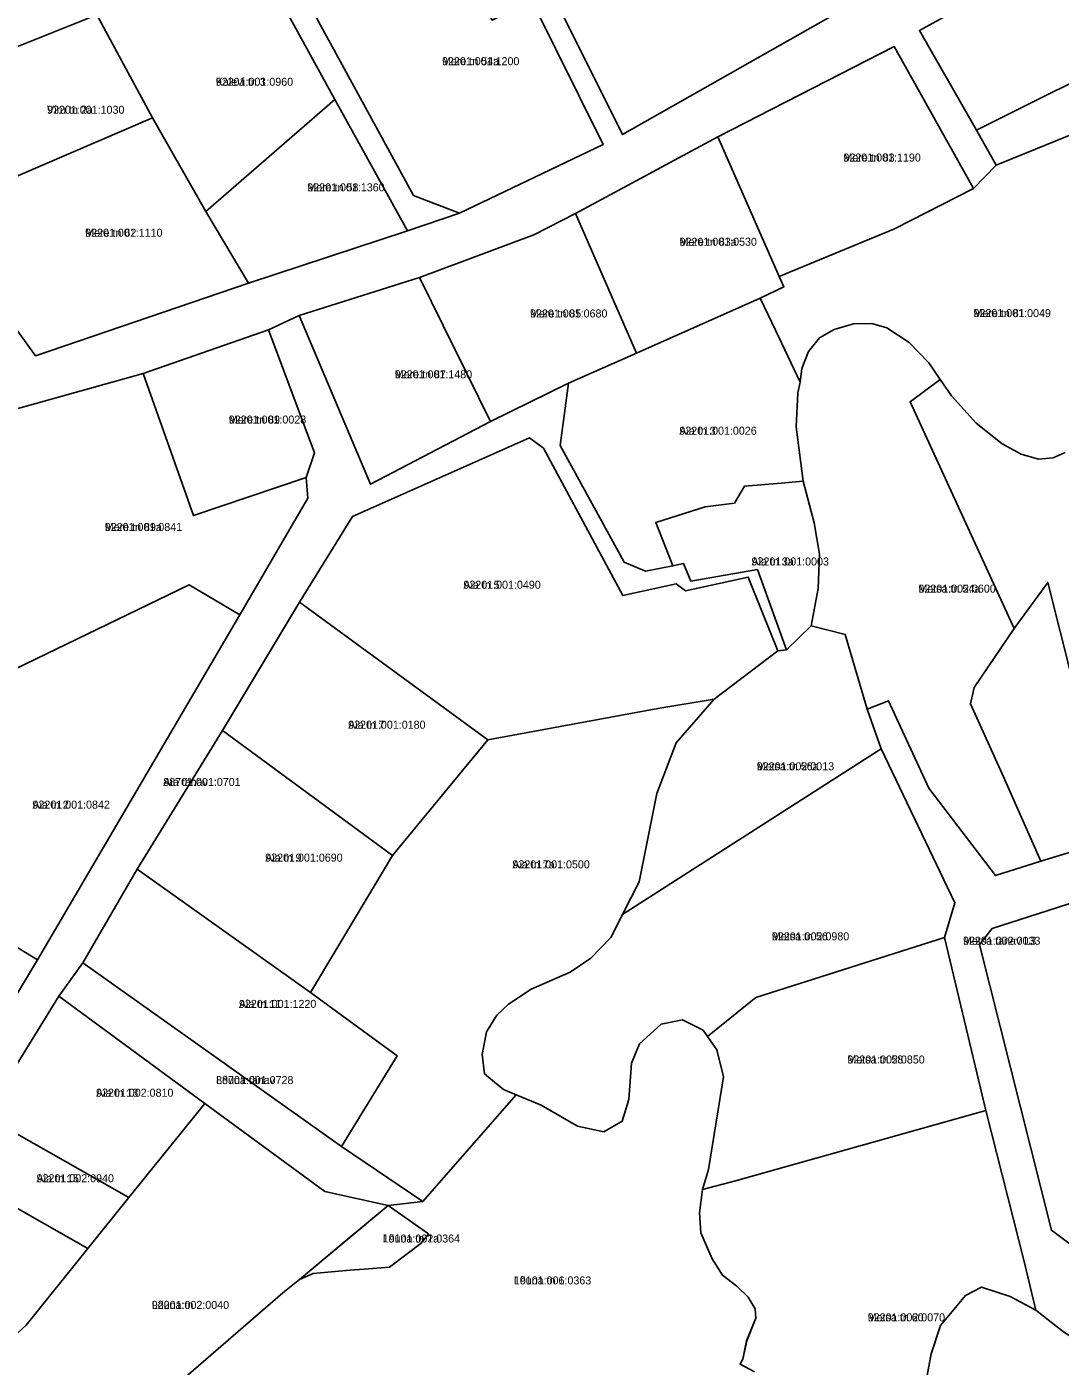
# Model space of a CAD drawing. Extents: x 601493 to 643081, y 6584980 to 6634019.
# Drawn here: x 610425.7 to 610619.4, y 6605570.9 to 6605821.9 of the extents above; entities that cross this region are included whole.
import ezdxf

# ---------------------------------------------------------------- set-up
doc = ezdxf.new("R2010")
doc.units = 0
for name, color, linetype in [('L_AADRESS', 7, 'Continuous'), ('PIIR', 7, 'Continuous'), ('TUNNUS', 7, 'Continuous')]:
    doc.layers.add(name, color=color, linetype=linetype)

msp = doc.modelspace()

# ---------------------------------------------------------------- linework, layer by layer
at = {"layer": 'PIIR'}
for points in [[(610409.51, 6605943.56), (610413.06, 6605945.52), (610442.84, 6605891.09), (610453, 6605873.21), (610473.31, 6605835.94), (610498.14, 6605790.29), (610506.76, 6605787.04), (610497.03, 6605783.72), (610483.4, 6605808.34), (610468.44, 6605835.69), (610458.2, 6605853.78), (610439.63, 6605888.64), (610429.91, 6605906.72)], [(610523.75, 6605829.01), (610538.97, 6605837.66), (610524.32, 6605864.07), (610549.39, 6605877.83), (610568.15, 6605844.43), (610579.58, 6605825.71), (610537.37, 6605801.75)], [(610407.64, 6605815.07), (610401, 6605826.74), (610398.53, 6605831.24), (610402.16, 6605833.25), (610458.2, 6605853.78), (610468.44, 6605835.69), (610438.77, 6605824.16), (610408.41, 6605812.08)], [(610473.31, 6605835.94), (610498.95, 6605849.93), (610512.93, 6605823.21), (610520.28, 6605826.94), (610533.7, 6605799.87), (610506.76, 6605787.04), (610498.14, 6605790.29)], [(610593.01, 6605821.27), (610636.89, 6605845.42), (610653.37, 6605817.46), (610639.31, 6605810.75), (610634.12, 6605817.74), (610603.72, 6605802.55)], [(610449.26, 6605804.89), (610438.77, 6605824.16), (610468.44, 6605835.69), (610483.4, 6605808.34), (610459.22, 6605787.33)], [(610401.39, 6605794.31), (610411.76, 6605799.04), (610408.41, 6605812.08), (610438.77, 6605824.16), (610449.26, 6605804.89), (610407.9, 6605787.12)], [(610566.71, 6605775.15), (610555.22, 6605801.29), (610588.26, 6605818.23), (610603.12, 6605791.61), (610588.35, 6605784.07)], [(610634.12, 6605817.74), (610639.31, 6605810.75), (610652.09, 6605787.88), (610652.85, 6605786.44), (610636.44, 6605776.8), (610622.16, 6605801.98), (610607.42, 6605796.01), (610603.72, 6605802.55)], [(610459.22, 6605787.33), (610483.4, 6605808.34), (610497.03, 6605783.72), (610467.24, 6605773.86)], [(610407.9, 6605787.12), (610449.26, 6605804.89), (610459.22, 6605787.33), (610467.24, 6605773.86), (610427.28, 6605760.29)], [(610539.94, 6605760.78), (610528.51, 6605786.94), (610555.22, 6605801.29), (610566.71, 6605775.15), (610567.56, 6605773.2), (610563.17, 6605771.06)], [(610499.29, 6605774.98), (610520.75, 6605782.97), (610528.51, 6605786.94), (610539.94, 6605760.78), (610527.23, 6605755.17), (610512.6, 6605747.99)], [(610490.07, 6605736.19), (610476.7, 6605767.8), (610499.29, 6605774.98), (610512.6, 6605747.99)], [(610527.23, 6605755.17), (610539.94, 6605760.78), (610563.17, 6605771.06), (610566, 6605765.1), (610570.64, 6605755.33), (610570.22, 6605753.32), (610569.87, 6605746.98), (610571.24, 6605736.77), (610567.08, 6605736.42), (610560.23, 6605735.85), (610558.31, 6605732.62), (610552.85, 6605731.98), (610543.56, 6605729), (610546.8, 6605720.92), (610541.66, 6605719.89), (610537.66, 6605721.59), (610525.67, 6605743.47)], [(610583.22, 6605694.06), (610579.09, 6605708.04), (610572.73, 6605709.65), (610574.02, 6605716.67), (610574.27, 6605723.1), (610573.29, 6605728.95), (610571.24, 6605736.77), (610569.87, 6605746.98), (610570.22, 6605753.32), (610570.64, 6605755.33), (610570.98, 6605757.9), (610572.19, 6605761.07), (610574.28, 6605763.67), (610577.03, 6605765.2), (610580.62, 6605766.25), (610584.1, 6605766.3), (610586.91, 6605765.53), (610591.06, 6605762.74), (610594.74, 6605758.98), (610596.92, 6605755.86), (610591.27, 6605751.67), (610610.74, 6605709.16), (610603.27, 6605698.07), (610602.57, 6605695.06), (610608.77, 6605681.37), (610615.77, 6605665.54), (610607.24, 6605662.85), (610594.78, 6605679.22), (610587.21, 6605695.63)], [(610447.51, 6605756.94), (610470.96, 6605765.17), (610479.57, 6605742.08), (610478.03, 6605737.44), (610456.9, 6605730.33)], [(610400.23, 6605743.76), (610447.51, 6605756.94), (610456.9, 6605730.33), (610478.03, 6605737.44), (610478.38, 6605733.58), (610465.58, 6605711.74), (610456.1, 6605717.35), (610415.85, 6605697.91)], [(610476.79, 6605714.12), (610486.71, 6605730.17), (610519.9, 6605744.92), (610522.53, 6605742.95), (610537.39, 6605715.33), (610547.42, 6605717.56), (610549.14, 6605716.22), (610560.92, 6605718.79), (610563.44, 6605712.42), (610566.49, 6605704.97), (610554.54, 6605695.93), (610543.95, 6605694.16), (610512.09, 6605688.29)], [(610543.56, 6605729), (610552.85, 6605731.98), (610558.31, 6605732.62), (610560.23, 6605735.85), (610567.08, 6605736.42), (610571.24, 6605736.77), (610573.29, 6605728.95), (610574.27, 6605723.1), (610574.02, 6605716.67), (610572.73, 6605709.65), (610568.08, 6605705.17), (610566.76, 6605708.81), (610562.66, 6605720.2), (610550.17, 6605718.04), (610548.75, 6605721.32), (610546.8, 6605720.92)], [(610387.89, 6605678.79), (610415.85, 6605697.91), (610456.1, 6605717.35), (610465.58, 6605711.74), (610427.67, 6605647.04), (610390.42, 6605669.77)], [(610608.77, 6605681.37), (610602.57, 6605695.06), (610603.27, 6605698.07), (610610.74, 6605709.16), (610617.06, 6605717.8), (610621.73, 6605699.44), (610633.98, 6605703.42), (610638.2, 6605691.66), (610644.68, 6605674.38), (610615.77, 6605665.54)], [(610512.09, 6605688.29), (610494.23, 6605666.62), (610462.38, 6605690.01), (610476.79, 6605714.12)], [(610572.73, 6605709.65), (610579.09, 6605708.04), (610583.22, 6605694.06), (610585.84, 6605686.6), (610546.41, 6605661.33), (610537.33, 6605655.52), (610540.49, 6605661.69), (610543.78, 6605678.25), (610547.4, 6605687.73), (610554.54, 6605695.93), (610566.49, 6605704.97), (610568.08, 6605705.17)], [(610527.51, 6605644.71), (610520.23, 6605641.56), (610515.98, 6605638.77), (610513.8, 6605636.71), (610511.86, 6605633.55), (610511.01, 6605629.3), (610511.49, 6605625.67), (610513.34, 6605624.14), (610515.01, 6605622.75), (610517.42, 6605621.76), (610513.38, 6605617.16), (610499.88, 6605601.76), (610484.69, 6605612.05), (610495.08, 6605629.08), (610478.88, 6605640.9), (610494.23, 6605666.62), (610512.09, 6605688.29), (610543.95, 6605694.16), (610554.54, 6605695.93), (610547.4, 6605687.73), (610543.78, 6605678.25), (610540.49, 6605661.69), (610537.33, 6605655.52), (610535.15, 6605651.26), (610531.39, 6605647.38)], [(610462.38, 6605690.01), (610494.23, 6605666.62), (610478.88, 6605640.9), (610446.34, 6605664.04)], [(610544.6, 6605634.99), (610540.53, 6605631.33), (610539.06, 6605627.68), (610538.54, 6605620.89), (610537.28, 6605616.81), (610533.84, 6605614.83), (610528.93, 6605615.87), (610522.07, 6605619.84), (610517.42, 6605621.76), (610515.01, 6605622.75), (610513.34, 6605624.14), (610511.49, 6605625.67), (610511.01, 6605629.3), (610511.86, 6605633.55), (610513.8, 6605636.71), (610515.98, 6605638.77), (610520.23, 6605641.56), (610527.51, 6605644.71), (610531.39, 6605647.38), (610535.15, 6605651.26), (610537.33, 6605655.52), (610546.41, 6605661.33), (610585.84, 6605686.6), (610599.65, 6605657.71), (610597.73, 6605651.24), (610562.34, 6605639.98), (610553.25, 6605632.7), (610552.44, 6605633.84), (610548.57, 6605635.82)], [(610382.27, 6605663.31), (610380.71, 6605667.07), (610390.42, 6605669.77), (610427.67, 6605647.04), (610404.86, 6605609.15), (610363.87, 6605656.09)], [(610446.34, 6605664.04), (610478.88, 6605640.9), (610495.08, 6605629.08), (610484.69, 6605612.05), (610436.17, 6605646.51)], [(610617.75, 6605596.36), (610604.29, 6605649.91), (610606.64, 6605652.9), (610629.58, 6605660.29), (610636.59, 6605616.03), (610658.53, 6605609.22), (610661.08, 6605608.5), (610661.53, 6605606.06), (610664.72, 6605596.68), (610669.26, 6605589.77), (610671.34, 6605586.86), (610672.35, 6605585.44), (610671.52, 6605581.73), (610669.15, 6605577.6), (610664.09, 6605574.82), (610653.47, 6605575.75), (610648.01, 6605576.06), (610646.85, 6605574.99), (610637.1, 6605581.95)], [(610552.34, 6605604.01), (610553.46, 6605607.77), (610556.27, 6605625.1), (610555.05, 6605630.18), (610553.25, 6605632.7), (610562.34, 6605639.98), (610597.73, 6605651.24), (610605.44, 6605618.8), (610558.54, 6605605.61)], [(610436.17, 6605646.51), (610484.69, 6605612.05), (610499.88, 6605601.76), (610493.38, 6605601), (610481.55, 6605603.61), (610459.02, 6605620.13), (610431.69, 6605640.26)], [(610431.69, 6605640.26), (610459.02, 6605620.13), (610444.82, 6605602.51), (610417.77, 6605617.8)], [(610425.55, 6605578.59), (610437.08, 6605592.92), (610444.82, 6605602.51), (610459.02, 6605620.13), (610481.55, 6605603.61), (610493.38, 6605601), (610476.79, 6605587.15), (610473.64, 6605584.61), (610451.8, 6605565.68), (610448.69, 6605563.75), (610435.15, 6605554.82), (610421.65, 6605548.04), (610419.3, 6605547.36), (610404.58, 6605543.12), (610393.75, 6605545.93), (610399.96, 6605555.08)], [(610417.77, 6605617.8), (610444.82, 6605602.51), (610437.08, 6605592.92), (610412.26, 6605607.05)], [(610412.26, 6605607.05), (610437.08, 6605592.92), (610425.55, 6605578.59), (610399.96, 6605555.08), (610383.24, 6605558.65)], [(610485.29, 6605594.26), (610493.38, 6605601), (610500.78, 6605595.79), (610500.98, 6605595.65), (610500.3, 6605594.82), (610499.56, 6605593.91), (610493.68, 6605589.47), (610488.91, 6605589.07), (610486.25, 6605588.85), (610479.34, 6605588.25), (610476.79, 6605587.15)]]:
    msp.add_lwpolyline(points, close=True, dxfattribs=at)
for points in [[(610636.89, 6605845.42), (610593.01, 6605821.27), (610603.72, 6605802.55), (610607.42, 6605796.01), (610603.12, 6605791.61), (610588.26, 6605818.23), (610555.22, 6605801.29), (610528.51, 6605786.94), (610520.75, 6605782.97), (610499.29, 6605774.98), (610476.7, 6605767.8), (610470.96, 6605765.17), (610447.51, 6605756.94), (610400.23, 6605743.76)], [(610523.75, 6605829.01), (610537.37, 6605801.75), (610579.58, 6605825.71)], [(610407.9, 6605787.12), (610427.28, 6605760.29), (610467.24, 6605773.86), (610497.03, 6605783.72), (610506.76, 6605787.04), (610533.7, 6605799.87), (610520.28, 6605826.94)], [(610620.36, 6605742.15), (610618.06, 6605741.14), (610615.34, 6605740.91), (610612.06, 6605741.84), (610608.5, 6605743.79), (610603.67, 6605747.67), (610599.04, 6605752.8), (610596.92, 6605755.86), (610594.74, 6605758.98), (610591.06, 6605762.74), (610586.91, 6605765.53), (610584.1, 6605766.3), (610580.62, 6605766.25), (610577.03, 6605765.2), (610574.28, 6605763.67), (610572.19, 6605761.07), (610570.98, 6605757.9), (610570.64, 6605755.33), (610566, 6605765.1), (610563.17, 6605771.06), (610567.56, 6605773.2), (610566.71, 6605775.15), (610588.35, 6605784.07), (610603.12, 6605791.61), (610607.42, 6605796.01), (610622.16, 6605801.98)], [(610404.86, 6605609.15), (610427.67, 6605647.04), (610465.58, 6605711.74), (610478.38, 6605733.58), (610478.03, 6605737.44), (610479.57, 6605742.08), (610470.96, 6605765.17), (610476.7, 6605767.8), (610490.07, 6605736.19), (610512.6, 6605747.99), (610527.23, 6605755.17), (610525.67, 6605743.47), (610537.66, 6605721.59), (610541.66, 6605719.89), (610546.8, 6605720.92), (610548.75, 6605721.32), (610550.17, 6605718.04), (610562.66, 6605720.2), (610566.76, 6605708.81), (610568.08, 6605705.17), (610566.49, 6605704.97), (610563.44, 6605712.42), (610560.92, 6605718.79), (610549.14, 6605716.22), (610547.42, 6605717.56), (610537.39, 6605715.33), (610522.53, 6605742.95), (610519.9, 6605744.92), (610486.71, 6605730.17), (610476.79, 6605714.12), (610462.38, 6605690.01), (610446.34, 6605664.04), (610436.17, 6605646.51), (610431.69, 6605640.26), (610417.77, 6605617.8)], [(610621.73, 6605699.44), (610617.06, 6605717.8), (610610.74, 6605709.16), (610591.27, 6605751.67), (610596.92, 6605755.86), (610599.04, 6605752.8), (610603.67, 6605747.67), (610608.5, 6605743.79), (610612.06, 6605741.84), (610615.34, 6605740.91), (610618.06, 6605741.14), (610620.36, 6605742.15)], [(610762.69, 6605727.65), (610736.99, 6605718.1), (610741.9, 6605692.35), (610736.92, 6605690.82), (610713.75, 6605683.91), (610696.11, 6605679.21), (610703.58, 6605649.99), (610698.8, 6605648.75), (610691.49, 6605678.3), (610680.02, 6605674.96), (610656.94, 6605668.21), (610629.58, 6605660.29), (610606.64, 6605652.9), (610604.29, 6605649.91), (610617.75, 6605596.36), (610637.1, 6605581.95), (610646.85, 6605574.99), (610645.12, 6605573.38), (610644.87, 6605572.95), (610641.1, 6605566.37)], [(610620, 6605577.34), (610614.85, 6605581.36), (610612.66, 6605590.5), (610605.44, 6605618.8), (610597.73, 6605651.24), (610599.65, 6605657.71), (610585.84, 6605686.6), (610583.22, 6605694.06), (610587.21, 6605695.63), (610594.78, 6605679.22), (610607.24, 6605662.85), (610615.77, 6605665.54), (610644.68, 6605674.38)], [(610451.8, 6605565.68), (610473.64, 6605584.61), (610476.79, 6605587.15), (610479.34, 6605588.25), (610486.25, 6605588.85), (610488.91, 6605589.07), (610493.68, 6605589.47), (610499.56, 6605593.91), (610500.3, 6605594.82), (610500.98, 6605595.65), (610500.78, 6605595.79), (610493.38, 6605601), (610499.88, 6605601.76), (610513.38, 6605617.16), (610517.42, 6605621.76), (610522.07, 6605619.84), (610528.93, 6605615.87), (610533.84, 6605614.83), (610537.28, 6605616.81), (610538.54, 6605620.89), (610539.06, 6605627.68), (610540.52, 6605631.33), (610544.6, 6605634.99), (610548.57, 6605635.82), (610552.44, 6605633.84), (610553.25, 6605632.7), (610555.05, 6605630.18), (610556.27, 6605625.1), (610553.46, 6605607.77), (610552.34, 6605604.01), (610551.77, 6605599.62), (610552.01, 6605595.88), (610554.13, 6605591), (610556.08, 6605587.92), (610558.76, 6605585.89), (610560.87, 6605583.85), (610562.2, 6605581.66), (610562.31, 6605579.87), (610560.62, 6605575.62), (610559.89, 6605572.22), (610559.38, 6605571.25), (610562.09, 6605569.82)], [(610562.09, 6605569.82), (610559.38, 6605571.25), (610559.89, 6605572.22), (610560.61, 6605575.62), (610562.31, 6605579.87), (610562.2, 6605581.66), (610560.87, 6605583.85), (610558.76, 6605585.89), (610556.08, 6605587.92), (610554.13, 6605591), (610552.01, 6605595.88), (610551.77, 6605599.62), (610552.34, 6605604.01), (610558.54, 6605605.61), (610605.44, 6605618.8), (610612.66, 6605590.5), (610614.85, 6605581.36), (610610.01, 6605583.94), (610604.65, 6605585.68), (610601.62, 6605584.11), (610596.98, 6605578.54), (610595.22, 6605573.18), (610593.98, 6605566.48)], [(610593.98, 6605566.48), (610595.22, 6605573.18), (610596.98, 6605578.54), (610601.62, 6605584.11), (610604.65, 6605585.68), (610610.01, 6605583.94), (610614.85, 6605581.36), (610620, 6605577.34), (610623.71, 6605574.97), (610625.67, 6605571.77), (610625.57, 6605568.47)]]:
    msp.add_lwpolyline(points, dxfattribs=at)

# ---------------------------------------------------------------- texts
at = {"layer": 'L_AADRESS'}
for s, p in [('Mere tn 54a', (610503.51, 6605814.75)), ('Kalevi tn 3', (610461.09, 6605810.89)), ('Viru tn 2a', (610429.46, 6605805.64)), ('Mere tn 83', (610578.76, 6605796.69)), ('Mere tn 58', (610478.25, 6605791.1)), ('Mere tn 62', (610436.61, 6605782.59)), ('Mere tn 83a', (610548.04, 6605780.9)), ('Mere tn 85', (610520.01, 6605767.46)), ('Mere tn 81', (610603.15, 6605767.53)), ('Mere tn 87', (610494.65, 6605756.05)), ('Mere tn 89', (610463.54, 6605747.57)), ('Aia tn 3', (610548, 6605745.48)), ('Mere tn 89a', (610440.28, 6605727.43)), ('Aia tn 3a', (610561.54, 6605720.97)), ('Aia tn 5', (610507.51, 6605716.61)), ('Metsa tn 54a', (610592.82, 6605715.88)), ('Aia tn 7', (610485.92, 6605690.37)), ('Metsa tn 56a', (610562.51, 6605682.58)), ('Aia tänav', (610451.25, 6605679.64)), ('Aia tn 2', (610426.73, 6605675.39)), ('Aia tn 9', (610470.37, 6605665.46)), ('Aia tn 7a', (610516.71, 6605664.2)), ('Metsa tn 56', (610565.35, 6605650.71)), ('Metsa tänav L3', (610601.18, 6605649.88)), ('Aia tn 11', (610465.44, 6605638.04)), ('Metsa tn 58', (610579.5, 6605627.62)), ('Lõuna tänav', (610461.15, 6605623.76)), ('Aia tn 13', (610438.65, 6605621.39)), ('Aia tn 15', (610427.5, 6605605.36)), ('Lõuna tn 2a', (610492.38, 6605594.07)), ('Lõuna tn 6', (610516.98, 6605586.21)), ('Lõuna tn 2', (610449.09, 6605581.62)), ('Metsa tn 60', (610583.31, 6605579.29))]:
    msp.add_text(s, height=1.5, dxfattribs=at).set_placement(p)
at = {"layer": 'TUNNUS'}
for s, p in [('92201:001:1200', (610503.51, 6605814.75)), ('92201:001:0960', (610461.09, 6605810.89)), ('92201:001:1030', (610429.46, 6605805.64)), ('92201:001:1190', (610578.76, 6605796.69)), ('92201:001:1360', (610478.25, 6605791.1)), ('92201:001:1110', (610436.61, 6605782.59)), ('92201:001:0530', (610548.04, 6605780.9)), ('92201:001:0680', (610520.01, 6605767.46)), ('92201:001:0049', (610603.15, 6605767.53)), ('92201:001:1480', (610494.65, 6605756.05)), ('92201:001:0028', (610463.54, 6605747.57)), ('92201:001:0026', (610548, 6605745.48)), ('92201:001:0841', (610440.28, 6605727.43)), ('92201:001:0003', (610561.54, 6605720.97)), ('92201:001:0490', (610507.51, 6605716.61)), ('92201:002:0600', (610592.82, 6605715.88)), ('92201:001:0180', (610485.92, 6605690.37)), ('92201:002:0013', (610562.51, 6605682.58)), ('88701:001:0701', (610451.25, 6605679.64)), ('92201:001:0842', (610426.73, 6605675.39)), ('92201:001:0690', (610470.37, 6605665.46)), ('92201:001:0500', (610516.71, 6605664.2)), ('92201:002:0980', (610565.35, 6605650.71)), ('92201:002:0033', (610601.18, 6605649.88)), ('92201:001:1220', (610465.44, 6605638.04)), ('92201:002:0850', (610579.5, 6605627.62)), ('88701:001:0728', (610461.15, 6605623.76)), ('92201:002:0810', (610438.65, 6605621.39)), ('92201:002:0940', (610427.5, 6605605.36)), ('19101:001:0364', (610492.38, 6605594.07)), ('19101:001:0363', (610516.98, 6605586.21)), ('92201:002:0040', (610449.09, 6605581.62)), ('92201:002:0070', (610583.31, 6605579.29))]:
    msp.add_text(s, height=1.5, dxfattribs=at).set_placement(p)

doc.saveas('drawing.dxf')
